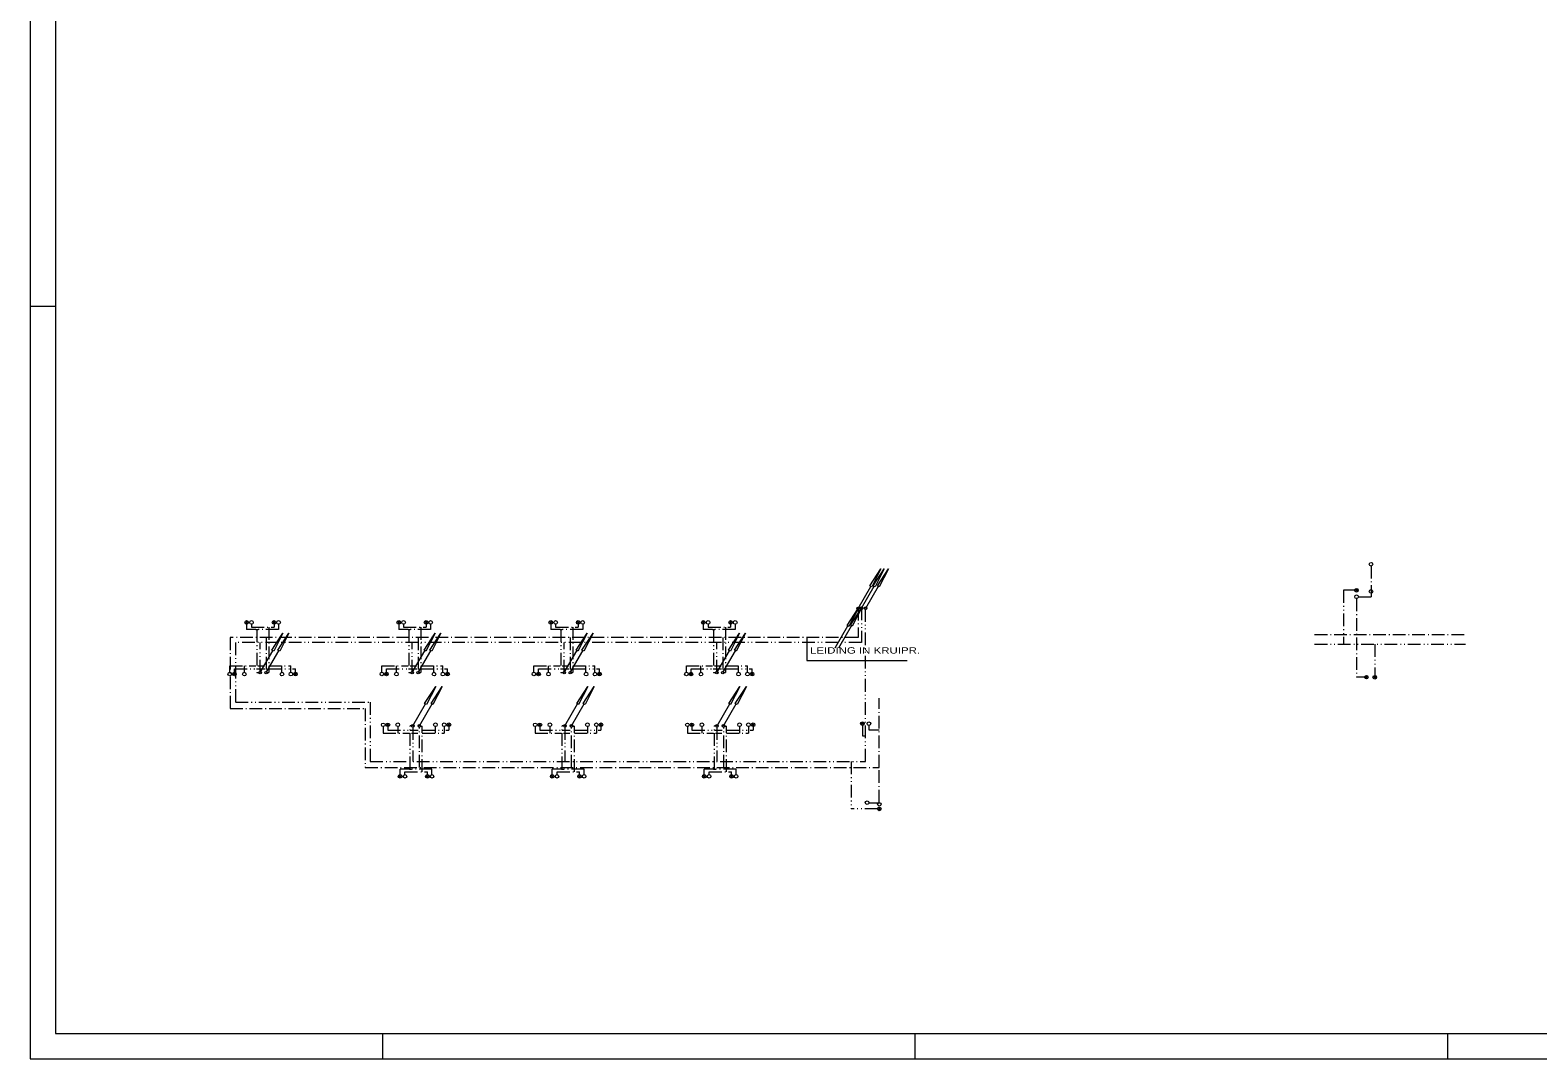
# Model space of a CAD drawing. Extents: x 295824 to 414724, y 24924 to 109024.
# Drawn here: x 295824 to 355274, y 24924 to 65507 of the extents above; entities that cross this region are included whole.
import ezdxf

# ---------------------------------------------------------------- set-up
doc = ezdxf.new("R2010")
doc.units = 0
doc.header["$LTSCALE"] = 100
doc.linetypes.add('DASH_DOUBLE_DOT', pattern=[9.2, 5, -1.2, 0.3, -1.2, 0.3, -1.2])
doc.linetypes.add('DOT_DASHED', pattern=[7.7, 5, -1.2, 0.3, -1.2])
for name, color, linetype, lineweight in [('1', 7, 'Continuous', 13), ('16', 7, 'Continuous', 13), ('30', 7, 'Continuous', 13)]:
    doc.layers.add(name, color=color, linetype=linetype, lineweight=lineweight)

msp = doc.modelspace()

# ---------------------------------------------------------------- linework, layer by layer
at = {"layer": '1'}
for p, q in [((295823.6, 109023.8), (295823.6, 24923.8)), ((295823.6, 54623.8), (296823.6, 54623.8)), ((309723.6, 24923.8), (309723.6, 25923.8)), ((330723.6, 24923.8), (330723.6, 25923.8)), ((351723.6, 24923.8), (351723.6, 25923.8)), ((295823.6, 24923.8), (304995.6, 24923.8)), ((304995.6, 24923.8), (414723.6, 24923.8))]:
    msp.add_line(p, q, dxfattribs=at)
for points in [[(304995.6, 108023.8), (296823.6, 108023.8), (296823.6, 25923.8), (304995.6, 25923.8)], [(304995.6, 25923.8), (413723.6, 25923.8), (413723.6, 108023.8), (304995.6, 108023.8)]]:
    msp.add_lwpolyline(points, dxfattribs=at)
at = {"layer": '30', "linetype": 'DOT_DASHED'}
for p, q in [((348695, 44380.4), (348695, 43152.6)), ((348124.5, 43080.9), (348124.5, 39981.8)), ((348196.2, 43152.6), (348695, 43152.6)), ((305235, 41959.3), (305235, 40163.5)), ((305439.1, 42067.2), (305439.1, 41955.8)), ((311231.4, 41959.3), (311231.4, 40163.5)), ((311435.4, 42067.2), (311435.4, 41955.8)), ((317227.7, 41959.3), (317227.7, 40163.5)), ((317431.8, 42067.2), (317431.8, 41955.8)), ((323240.8, 41959.3), (323240.8, 40163.5)), ((323444.8, 42067.2), (323444.8, 41955.8)), ((346472.9, 41666.4), (352419.3, 41666.4)), ((305126.8, 41549.4), (305126.8, 40184.8)), ((311123.1, 41549.4), (311123.1, 40184.8)), ((317119.5, 41549.4), (317119.5, 40184.8)), ((323132.5, 41549.4), (323132.5, 40184.8)), ((303694.3, 40177.3), (303694.3, 40431.8)), ((303694.3, 40431.8), (304727, 40431.8)), ((304270, 40175.3), (304270, 40431.8)), ((304806.1, 40431.8), (305060.1, 40431.8)), ((305235, 40431.8), (306102.2, 40431.8)), ((305748.2, 40175.3), (305748.2, 40431.8)), ((306102.2, 40175.3), (306102.2, 40431.8)), ((309690.7, 40177.3), (309690.7, 40431.8)), ((309690.7, 40431.8), (310723.4, 40431.8)), ((310266.3, 40175.3), (310266.3, 40431.8)), ((310802.5, 40431.8), (311056.5, 40431.8)), ((311231.4, 40431.8), (312098.5, 40431.8)), ((311744.6, 40175.3), (311744.6, 40431.8)), ((312098.5, 40175.3), (312098.5, 40431.8)), ((315687, 40177.3), (315687, 40431.8)), ((315687, 40431.8), (316719.7, 40431.8)), ((316262.7, 40175.3), (316262.7, 40431.8)), ((316798.8, 40431.8), (317052.8, 40431.8)), ((317227.7, 40431.8), (318094.9, 40431.8)), ((317740.9, 40175.3), (317740.9, 40431.8)), ((318094.9, 40175.3), (318094.9, 40431.8)), ((321700.1, 40177.3), (321700.1, 40431.8)), ((321700.1, 40431.8), (322732.7, 40431.8)), ((322275.7, 40175.3), (322275.7, 40431.8)), ((322811.9, 40431.8), (323065.9, 40431.8)), ((323240.8, 40431.8), (324107.9, 40431.8)), ((323754, 40175.3), (323754, 40431.8)), ((324107.9, 40175.3), (324107.9, 40431.8)), ((305172.5, 40163.5), (305235, 40163.5)), ((311168.9, 40163.5), (311231.4, 40163.5)), ((317165.3, 40163.5), (317227.7, 40163.5)), ((323178.3, 40163.5), (323240.8, 40163.5)), ((329298.2, 36416.2), (329298.2, 39149.4)), ((309744.9, 38029.9), (309744.9, 37775.3)), ((309744.9, 37775.3), (310777.6, 37775.3)), ((310320.6, 38031.9), (310320.6, 37775.3)), ((310856.7, 37775.3), (311110.7, 37775.3)), ((311177.4, 36416.2), (311177.4, 38022.4)), ((311223.2, 38043.7), (311285.6, 38043.7)), ((311285.6, 36247.8), (311285.6, 38043.7)), ((311285.6, 37775.3), (312152.8, 37775.3)), ((311798.8, 38031.9), (311798.8, 37775.3)), ((312152.8, 38031.9), (312152.8, 37775.3)), ((315741.2, 38029.9), (315741.2, 37775.3)), ((315741.2, 37775.3), (316773.9, 37775.3)), ((316316.9, 38031.9), (316316.9, 37775.3)), ((316853, 37775.3), (317107, 37775.3)), ((317173.7, 36416.2), (317173.7, 38022.4)), ((317219.5, 38043.7), (317281.9, 38043.7)), ((317281.9, 36247.8), (317281.9, 38043.7)), ((317281.9, 37775.3), (318149.1, 37775.3)), ((317795.1, 38031.9), (317795.1, 37775.3)), ((318149.1, 38031.9), (318149.1, 37775.3)), ((321737.5, 38029.9), (321737.5, 37775.3)), ((321737.5, 37775.3), (322770.2, 37775.3)), ((322313.2, 38031.9), (322313.2, 37775.3)), ((322849.3, 37775.3), (323103.3, 37775.3)), ((323170, 36416.2), (323170, 38022.4)), ((323215.8, 38043.7), (323278.2, 38043.7)), ((323278.2, 36247.8), (323278.2, 38043.7)), ((323278.2, 37775.3), (324145.4, 37775.3)), ((323791.4, 38031.9), (323791.4, 37775.3)), ((324145.4, 38031.9), (324145.4, 37775.3)), ((329306.8, 35036.8), (329306.8, 36416.2)), ((311489.7, 36140), (311489.7, 36251.4)), ((317486, 36140), (317486, 36251.4)), ((323482.3, 36140), (323482.3, 36251.4)), ((328895.7, 35027.8), (329312.1, 35027.8))]:
    msp.add_line(p, q, dxfattribs=at)
at = {"layer": '30'}
for p, q in [((328470.9, 42694.4), (328970.9, 43560.4)), ((328604.2, 42702.7), (329104.2, 43568.7)), ((328770.7, 42702.7), (329270.7, 43568.7)), ((348172, 43361.3), (348070.6, 43462.7)), ((348174, 43458.5), (348072.9, 43357.3)), ((304408, 42192.6), (304306.8, 42091.5)), ((304310.9, 42190.5), (304412.2, 42089.2)), ((305486.5, 42192.6), (305385.3, 42091.5)), ((305389.3, 42190.5), (305490.7, 42089.2)), ((310404.4, 42192.6), (310303.2, 42091.5)), ((310307.2, 42190.5), (310408.6, 42089.2)), ((311482.9, 42192.6), (311381.7, 42091.5)), ((311385.7, 42190.5), (311487, 42089.2)), ((316400.7, 42192.6), (316299.6, 42091.5)), ((316303.6, 42190.5), (316404.9, 42089.2)), ((317479.2, 42192.6), (317378.1, 42091.5)), ((317382.1, 42190.5), (317483.4, 42089.2)), ((322413.7, 42192.6), (322312.6, 42091.5)), ((322316.6, 42190.5), (322417.9, 42089.2)), ((323492.2, 42192.6), (323391.1, 42091.5)), ((323395.1, 42190.5), (323496.4, 42089.2)), ((327570.9, 41135.4), (328070.9, 42001.4)), ((327704.2, 41143.7), (328204.2, 42009.7)), ((304893.6, 40159.8), (305393.6, 41025.8)), ((305126.8, 40159.8), (305626.8, 41025.8)), ((310889.9, 40159.8), (311389.9, 41025.8)), ((311123.1, 40159.8), (311623.1, 41025.8)), ((316886.3, 40159.8), (317386.3, 41025.8)), ((317119.5, 40159.8), (317619.5, 41025.8)), ((322899.3, 40159.8), (323399.3, 41025.8)), ((323132.5, 40159.8), (323632.5, 41025.8)), ((326442.7, 41538.5), (326442.7, 40638.5)), ((326442.7, 40638.5), (330401.9, 40638.5)), ((303925, 40159.3), (303823.8, 40058.2)), ((303827.8, 40157.2), (303929.2, 40055.9)), ((306332.8, 40157.3), (306231.6, 40056.2)), ((306235.7, 40155.3), (306337, 40053.9)), ((309921.3, 40159.3), (309820.2, 40058.2)), ((309824.2, 40157.2), (309925.5, 40055.9)), ((312329.2, 40157.3), (312228, 40056.2)), ((312232, 40155.3), (312333.4, 40053.9)), ((315917.7, 40159.3), (315816.5, 40058.2)), ((315820.5, 40157.2), (315921.9, 40055.9)), ((318325.5, 40157.3), (318224.4, 40056.2)), ((318228.4, 40155.3), (318329.7, 40053.9)), ((321930.7, 40159.3), (321829.5, 40058.2)), ((321833.6, 40157.2), (321934.9, 40055.9)), ((324338.5, 40157.3), (324237.4, 40056.2)), ((324241.4, 40155.3), (324342.7, 40053.9)), ((348896.5, 39928), (348795.2, 40029.3)), ((348898.6, 40025.1), (348797.5, 39924)), ((310915, 38059.8), (311415, 38925.8)), ((311171.2, 38059.8), (311671.2, 38925.8)), ((316911.4, 38059.8), (317411.4, 38925.8)), ((317167.5, 38059.8), (317667.5, 38925.8)), ((322907.7, 38059.8), (323407.7, 38925.8)), ((323163.8, 38059.8), (323663.8, 38925.8)), ((309975.6, 38047.9), (309874.4, 38149)), ((309878.4, 38050), (309979.8, 38151.3)), ((312383.4, 38049.8), (312282.3, 38151)), ((312286.3, 38051.9), (312387.6, 38153.3)), ((315971.9, 38047.9), (315870.7, 38149)), ((315874.7, 38050), (315976.1, 38151.3)), ((318379.7, 38049.8), (318278.6, 38151)), ((318282.6, 38051.9), (318383.9, 38153.3)), ((321968.2, 38047.9), (321867, 38149)), ((321871, 38050), (321972.4, 38151.3)), ((324376, 38049.8), (324274.9, 38151)), ((324278.9, 38051.9), (324380.2, 38153.3)), ((328692.2, 38098.8), (328590.8, 38200.2)), ((328694.2, 38196), (328593.1, 38094.8)), ((310458.6, 36014.6), (310357.5, 36115.7)), ((310361.5, 36016.7), (310462.8, 36118)), ((311537.1, 36014.6), (311436, 36115.7)), ((311440, 36016.7), (311541.3, 36118)), ((316454.9, 36014.6), (316353.8, 36115.7)), ((316357.8, 36016.7), (316459.1, 36118)), ((317533.4, 36014.6), (317432.3, 36115.7)), ((317436.3, 36016.7), (317537.6, 36118)), ((322451.2, 36014.6), (322350.1, 36115.7)), ((322354.1, 36016.7), (322455.4, 36118)), ((323529.7, 36014.6), (323428.6, 36115.7)), ((323432.6, 36016.7), (323533.9, 36118)), ((329358.4, 34736.4), (329257.1, 34837.7)), ((329360.5, 34833.5), (329259.4, 34732.4))]:
    msp.add_line(p, q, dxfattribs=at)
at = {"layer": '30', "linetype": 'DASH_DOUBLE_DOT'}
for p, q in [((348048.7, 43411), (347605.5, 43411)), ((347605.5, 43411), (347605.5, 41283.1)), ((328598.6, 42724.4), (328598.6, 41349.4)), ((328765.2, 36649.5), (328765.2, 42672.7)), ((304360.6, 42067.2), (304360.6, 41857.8)), ((304727, 41857.8), (304360.6, 41857.8)), ((304727, 41857.8), (304814.4, 41857.8)), ((304760.3, 41857.8), (304760.3, 40155.2)), ((305618.1, 41857.8), (304814.4, 41857.8)), ((305618.1, 42067.2), (305618.1, 41857.8)), ((310356.9, 42067.2), (310356.9, 41857.8)), ((310723.4, 41857.8), (310356.9, 41857.8)), ((310723.4, 41857.8), (310810.8, 41857.8)), ((310756.7, 41857.8), (310756.7, 40155.2)), ((311614.5, 41857.8), (310810.8, 41857.8)), ((311614.5, 42067.2), (311614.5, 41857.8)), ((316353.3, 42067.2), (316353.3, 41857.8)), ((316719.7, 41857.8), (316353.3, 41857.8)), ((316719.7, 41857.8), (316807.2, 41857.8)), ((316753, 41857.8), (316753, 40155.2)), ((317610.8, 41857.8), (316807.2, 41857.8)), ((317610.8, 42067.2), (317610.8, 41857.8)), ((322366.3, 42067.2), (322366.3, 41857.8)), ((322732.7, 41857.8), (322366.3, 41857.8)), ((322732.7, 41857.8), (322820.2, 41857.8)), ((322766, 41857.8), (322766, 40155.2)), ((323623.9, 41857.8), (322820.2, 41857.8)), ((323623.9, 42067.2), (323623.9, 41857.8)), ((328598.6, 41349.4), (303922.4, 41349.4)), ((304893.6, 40159.8), (304893.6, 41349.4)), ((310889.9, 40159.8), (310889.9, 41349.4)), ((316886.3, 40159.8), (316886.3, 41349.4)), ((322899.3, 40159.8), (322899.3, 41349.4)), ((346472.9, 41283.1), (352419.3, 41283.1)), ((348844.9, 41283.1), (348844.9, 40049.8)), ((303877.5, 40177.3), (303877.5, 40311)), ((304843.6, 40155.2), (304760.3, 40155.2)), ((305248.3, 40311), (306285.4, 40311)), ((306285.4, 40175.3), (306285.4, 40311)), ((309873.9, 40177.3), (309873.9, 40311)), ((310839.9, 40155.2), (310756.7, 40155.2)), ((311244.7, 40311), (312281.7, 40311)), ((312281.7, 40175.3), (312281.7, 40311)), ((315870.2, 40177.3), (315870.2, 40311)), ((316836.3, 40155.2), (316753, 40155.2)), ((317241, 40311), (318278.1, 40311)), ((318278.1, 40175.3), (318278.1, 40311)), ((321883.3, 40177.3), (321883.3, 40311)), ((322849.3, 40155.2), (322766, 40155.2)), ((323254, 40311), (324291.1, 40311)), ((324291.1, 40175.3), (324291.1, 40311)), ((310866.9, 38060.3), (310810.9, 38060.3)), ((310810.9, 36349.3), (310810.9, 38060.3)), ((316863.2, 38060.3), (316807.2, 38060.3)), ((316807.2, 36349.3), (316807.2, 38060.3)), ((322859.5, 38060.3), (322803.5, 38060.3)), ((322803.5, 36349.3), (322803.5, 38060.3)), ((328640.5, 38076.9), (328640.5, 37661.1)), ((309928.1, 38029.9), (309928.1, 37896.2)), ((310910.9, 38014.1), (310910.9, 36649.5)), ((311298.9, 37896.2), (312336, 37896.2)), ((312336, 38031.9), (312336, 37896.2)), ((315924.4, 38029.9), (315924.4, 37896.2)), ((316907.2, 38014.1), (316907.2, 36649.5)), ((317295.2, 37896.2), (318332.3, 37896.2)), ((318332.3, 38031.9), (318332.3, 37896.2)), ((321920.7, 38029.9), (321920.7, 37896.2)), ((322903.5, 38014.1), (322903.5, 36649.5)), ((323291.5, 37896.2), (324328.6, 37896.2)), ((324328.6, 38031.9), (324328.6, 37896.2)), ((328640.5, 37661.1), (328765.2, 37661.1)), ((310411.2, 36140), (310411.2, 36349.3)), ((310777.6, 36349.3), (310411.2, 36349.3)), ((310777.6, 36349.3), (310865, 36349.3)), ((311668.7, 36349.3), (310865, 36349.3)), ((311668.7, 36140), (311668.7, 36349.3)), ((316407.5, 36140), (316407.5, 36349.3)), ((316773.9, 36349.3), (316407.5, 36349.3)), ((316773.9, 36349.3), (316861.4, 36349.3)), ((317665, 36349.3), (316861.4, 36349.3)), ((317665, 36140), (317665, 36349.3)), ((322403.8, 36140), (322403.8, 36349.3)), ((322770.2, 36349.3), (322403.8, 36349.3)), ((322770.2, 36349.3), (322857.7, 36349.3)), ((323661.3, 36349.3), (322857.7, 36349.3)), ((323661.3, 36140), (323661.3, 36349.3)), ((328196.1, 36652.8), (328196.1, 34786.1)), ((329235.1, 34786.1), (328196.1, 34786.1))]:
    msp.add_line(p, q, dxfattribs=at)
at = {"layer": '30'}
for points in [[(329370.9, 44253.4), (329006.9, 43539.4), (328934.9, 43581.4)], [(329504.2, 44261.7), (329140.2, 43547.7), (329068.2, 43589.7)], [(329670.7, 44261.7), (329306.7, 43547.7), (329234.7, 43589.7)], [(328470.9, 42694.4), (328106.9, 41980.4), (328034.9, 42022.4)], [(328604.2, 42702.7), (328240.2, 41988.7), (328168.2, 42030.7)], [(305793.6, 41718.8), (305429.6, 41004.8), (305357.6, 41046.8)], [(306026.8, 41718.8), (305662.8, 41004.8), (305590.8, 41046.8)], [(311789.9, 41718.8), (311425.9, 41004.8), (311353.9, 41046.8)], [(312023.1, 41718.8), (311659.1, 41004.8), (311587.1, 41046.8)], [(317786.3, 41718.8), (317422.3, 41004.8), (317350.3, 41046.8)], [(318019.5, 41718.8), (317655.5, 41004.8), (317583.5, 41046.8)], [(323799.3, 41718.8), (323435.3, 41004.8), (323363.3, 41046.8)], [(324032.5, 41718.8), (323668.5, 41004.8), (323596.5, 41046.8)], [(311815, 39618.8), (311451, 38904.8), (311379, 38946.8)], [(312071.2, 39618.8), (311707.2, 38904.8), (311635.2, 38946.8)], [(317811.4, 39618.8), (317447.4, 38904.8), (317375.4, 38946.8)], [(318067.5, 39618.8), (317703.5, 38904.8), (317631.5, 38946.8)], [(323807.7, 39618.8), (323443.7, 38904.8), (323371.7, 38946.8)], [(324063.8, 39618.8), (323699.8, 38904.8), (323627.8, 38946.8)]]:
    msp.add_lwpolyline(points, close=True, dxfattribs=at)
at = {"layer": '30', "linetype": 'DOT_DASHED'}
for points in [[(328473.7, 42716), (328473.7, 41549.4), (303705.8, 41549.4), (303705.8, 38749.5), (309035.8, 38749.5), (309035.8, 36416.2), (329298.2, 36416.2)], [(304552.1, 42067.2), (304552.1, 41955.8), (305439.1, 41955.8)], [(310548.5, 42067.2), (310548.5, 41955.8), (311435.4, 41955.8)], [(316544.8, 42067.2), (316544.8, 41955.8), (317431.8, 41955.8)], [(322557.9, 42067.2), (322557.9, 41955.8), (323444.8, 41955.8)], [(348440.1, 39981.8), (348538.3, 39981.8), (348124.5, 39981.8)], [(328894.5, 38076.8), (328894.5, 37902.8), (329298.2, 37902.8)], [(310602.7, 36140), (310602.7, 36251.4), (311489.7, 36251.4)], [(316599, 36140), (316599, 36251.4), (317486, 36251.4)], [(322595.3, 36140), (322595.3, 36251.4), (323482.3, 36251.4)]]:
    msp.add_lwpolyline(points, dxfattribs=at)
at = {"layer": '30', "linetype": 'DASH_DOUBLE_DOT'}
for points in [[(303922.4, 41349.4), (303922.4, 38991.1), (309235.7, 38991.1), (309235.7, 36649.5), (328765.2, 36649.5)], [(303877.5, 40311), (304760.3, 40311), (305073.4, 40311)], [(309873.9, 40311), (310756.7, 40311), (311069.8, 40311)], [(315870.2, 40311), (316753, 40311), (317066.1, 40311)], [(321883.3, 40311), (322766, 40311), (323079.2, 40311)], [(309928.1, 37896.2), (310810.9, 37896.2), (311124, 37896.2)], [(315924.4, 37896.2), (316807.2, 37896.2), (317120.3, 37896.2)], [(321920.7, 37896.2), (322803.5, 37896.2), (323116.6, 37896.2)]]:
    msp.add_lwpolyline(points, dxfattribs=at)
at = {"layer": '30'}
for centre, radius in [((348695, 44436.1), 71.7), ((348120.3, 43411), 71.7), ((348695, 43365.1), 71.7), ((348124.5, 43152.6), 71.7), ((304360.6, 42138.9), 71.7), ((304552.1, 42138.9), 71.7), ((305439.1, 42138.9), 71.7), ((305618.1, 42138.9), 71.7), ((310356.9, 42138.9), 71.7), ((310548.5, 42138.9), 71.7), ((311435.4, 42138.9), 71.7), ((311614.5, 42138.9), 71.7), ((316353.3, 42138.9), 71.7), ((316544.8, 42138.9), 71.7), ((317431.8, 42138.9), 71.7), ((317610.8, 42138.9), 71.7), ((322366.3, 42138.9), 71.7), ((322557.9, 42138.9), 71.7), ((323444.8, 42138.9), 71.7), ((323623.9, 42138.9), 71.7), ((328470.9, 42694.1), 50), ((328470.9, 42694.1), 50), ((328604.2, 42702.4), 50), ((328604.2, 42702.4), 50), ((328770.7, 42702.4), 50), ((303694.3, 40105.6), 71.7), ((303877.5, 40105.6), 71.7), ((304270, 40103.7), 71.7), ((304893.6, 40159.5), 50), ((305126.8, 40159.5), 50), ((305752.4, 40103.7), 71.7), ((306102.2, 40103.7), 71.7), ((306285.4, 40103.6), 71.7), ((309690.7, 40105.6), 71.7), ((309873.9, 40105.6), 71.7), ((310266.3, 40103.7), 71.7), ((310889.9, 40159.5), 50), ((311123.1, 40159.5), 50), ((311748.7, 40103.7), 71.7), ((312098.5, 40103.7), 71.7), ((312281.7, 40103.6), 71.7), ((315687, 40105.6), 71.7), ((315870.3, 40105.6), 71.7), ((316262.7, 40103.7), 71.7), ((316886.3, 40159.5), 50), ((317119.5, 40159.5), 50), ((317745.1, 40103.7), 71.7), ((318094.9, 40103.7), 71.7), ((318278.1, 40103.6), 71.7), ((321700.1, 40105.6), 71.7), ((321883.3, 40105.6), 71.7), ((322275.7, 40103.7), 71.7), ((322899.3, 40159.5), 50), ((323132.5, 40159.5), 50), ((323758.1, 40103.7), 71.7), ((324107.9, 40103.7), 71.7), ((324291.1, 40103.6), 71.7), ((348511.8, 39981.8), 71.7), ((348844.9, 39977.7), 71.7), ((309744.9, 38101.6), 71.7), ((309928.2, 38101.6), 71.7), ((310320.6, 38103.5), 71.7), ((310915, 38059.5), 50), ((311171.1, 38059.5), 50), ((311803, 38103.5), 71.7), ((312152.8, 38103.5), 71.7), ((312336, 38103.6), 71.7), ((315741.2, 38101.6), 71.7), ((315924.5, 38101.6), 71.7), ((316316.9, 38103.5), 71.7), ((316911.3, 38059.5), 50), ((317167.4, 38059.5), 50), ((317799.3, 38103.5), 71.7), ((318149.1, 38103.5), 71.7), ((318332.3, 38103.6), 71.7), ((321737.5, 38101.6), 71.7), ((321920.8, 38101.6), 71.7), ((322313.2, 38103.5), 71.7), ((322907.6, 38059.5), 50), ((323163.7, 38059.5), 50), ((323795.6, 38103.5), 71.7), ((324145.4, 38103.5), 71.7), ((324328.6, 38103.6), 71.7), ((328640.5, 38148.6), 71.7), ((328894.5, 38148.4), 71.7), ((310411.2, 36068.3), 71.7), ((310602.7, 36068.3), 71.7), ((311489.7, 36068.3), 71.7), ((311668.7, 36068.3), 71.7), ((316407.5, 36068.3), 71.7), ((316599, 36068.3), 71.7), ((317486, 36068.3), 71.7), ((317665, 36068.3), 71.7), ((322403.8, 36068.3), 71.7), ((322595.3, 36068.3), 71.7), ((323482.3, 36068.3), 71.7), ((323661.3, 36068.3), 71.7), ((328823.8, 35031.8), 71.7), ((329306.8, 34965.2), 71.7), ((329306.8, 34786.1), 71.7)]:
    msp.add_circle(centre, radius, dxfattribs=at)

# ---------------------------------------------------------------- texts
at = {"layer": '16', "width": 1.35}
msp.add_text('LEIDING IN KRUIPR.', height=250, dxfattribs=at).set_placement((326574.3, 40912.2))

doc.saveas('drawing.dxf')
